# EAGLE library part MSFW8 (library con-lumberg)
MSF CONNECTOR
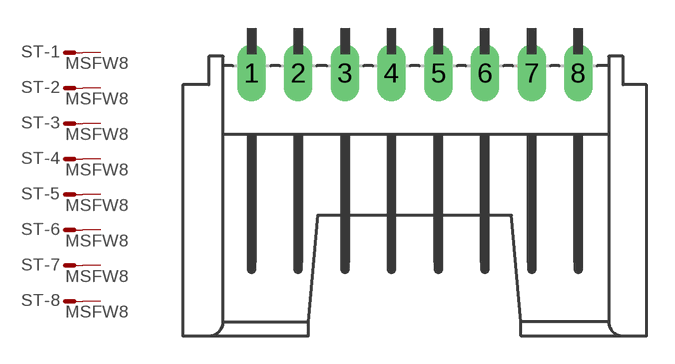
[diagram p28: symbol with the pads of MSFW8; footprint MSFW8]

Designator prefix ST; gates -1=M -2=M -3=M -4=M -5=M -6=M -7=M -8=M

## MSFW8 (OC_FARNELL: unknown; OC_NEWARK: unknown)  [MSFW8]
1  -1:S  pas
2  -2:S  pas
3  -3:S  pas
4  -4:S  pas
5  -5:S  pas
6  -6:S  pas
7  -7:S  pas
8  -8:S  pas

## Footprint MSFW8 (pad centres in mm)
MSF CONNECTOR
drill 1.016 long: 1 0,1.905; 2 2.489,1.905; 3 5.004,1.905; 4 7.493,1.905; 5 10.008,1.905; 6 12.497,1.905; 7 15.011,1.905; 8 17.501,1.905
